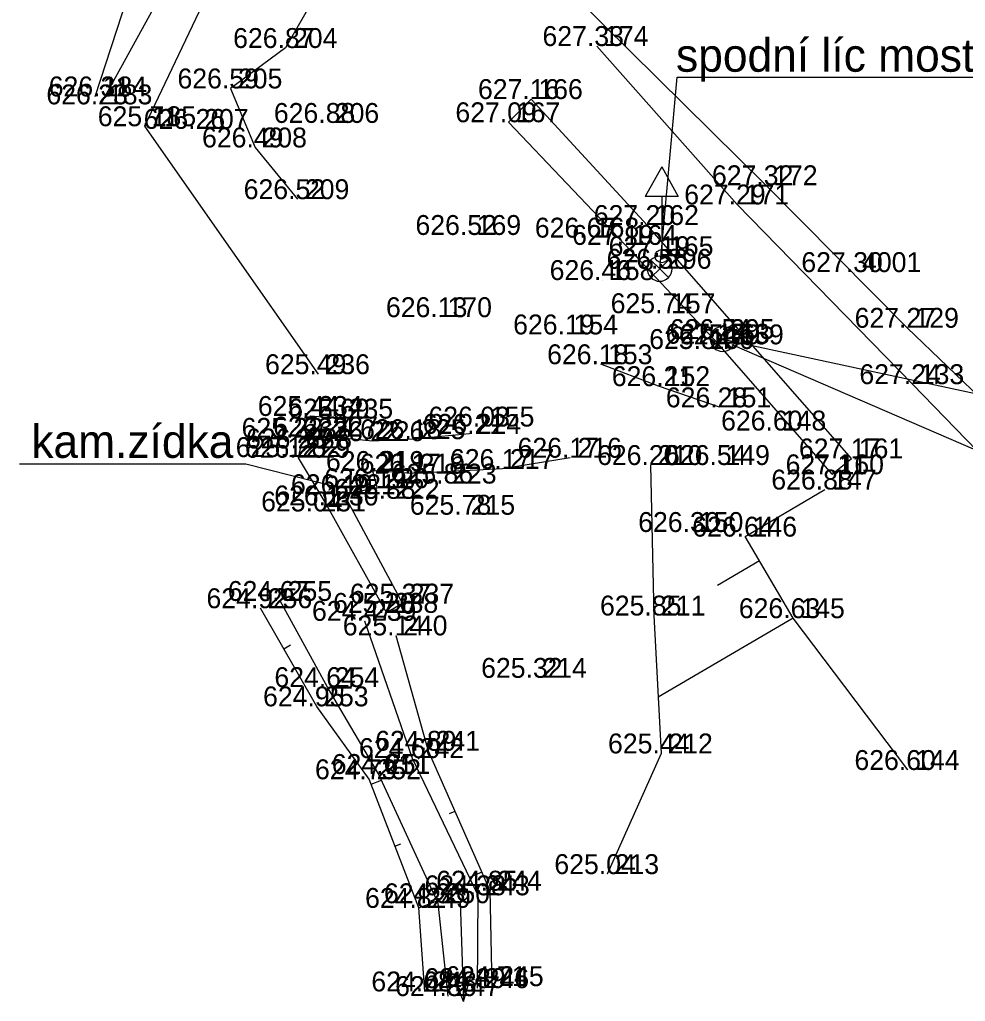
# Model space of a CAD drawing. Extents: x -632073 to -631949, y -1099530 to -1099406.
# Drawn here: x -632009.68 to -631995.42, y -1099504.03 to -1099489.22 of the extents above; entities that cross this region are included whole.
import ezdxf

# ---------------------------------------------------------------- set-up
doc = ezdxf.new("R2010")
doc.units = 0
for name, color, linetype in [('Vrstva 1', 7, 'Continuous'), ('Vrstva 13', 7, 'Continuous'), ('Vrstva 14', 7, 'Continuous'), ('Vrstva 15', 7, 'Continuous'), ('Vrstva 19', 7, 'Continuous'), ('Vrstva 20', 7, 'Continuous'), ('Vrstva 22', 7, 'Continuous'), ('Vrstva 23', 7, 'Continuous'), ('Vrstva 26', 7, 'Continuous'), ('Vrstva 27', 7, 'Continuous'), ('Vrstva 5', 7, 'Continuous'), ('Vrstva 6', 7, 'Continuous'), ('Vrstva 7', 7, 'Continuous'), ('Vrstva 8', 7, 'Continuous'), ('Vrstva 9', 7, 'Continuous')]:
    doc.layers.add(name, color=color, linetype=linetype)

msp = doc.modelspace()

# ---------------------------------------------------------------- linework, layer by layer
at = {"layer": 'Vrstva 1'}
for p, q in [((-631998.86, -1099492.01), (-632000.98, -1099489.62)), ((-631996.22, -1099494.72), (-631998.86, -1099492.01)), ((-631993.26, -1099497.78), (-631996.22, -1099494.72))]:
    msp.add_line(p, q, dxfattribs=at)
at = {"layer": 'Vrstva 13'}
for p, q in [((-632000.98, -1099489.62), (-632000.98, -1099489.62)), ((-632005.67, -1099489.65), (-632005.67, -1099489.65)), ((-632006.5, -1099490.26), (-632006.5, -1099490.26)), ((-632008.54, -1099490.38), (-632008.54, -1099490.38)), ((-632008.46, -1099490.5), (-632008.46, -1099490.5)), ((-632001.97, -1099490.42), (-632001.97, -1099490.42)), ((-632005.04, -1099490.78), (-632005.04, -1099490.78)), ((-632002.31, -1099490.77), (-632002.31, -1099490.77)), ((-632007.8, -1099490.83), (-632007.8, -1099490.83)), ((-632007.01, -1099490.87), (-632007.01, -1099490.87)), ((-632006.13, -1099491.15), (-632006.13, -1099491.15)), ((-631998.43, -1099491.72), (-631998.43, -1099491.72)), ((-632005.49, -1099491.93), (-632005.49, -1099491.93)), ((-631998.86, -1099492.01), (-631998.86, -1099492.01)), ((-632000.22, -1099492.32), (-632000.22, -1099492.32)), ((-632002.9, -1099492.47), (-632002.9, -1099492.47)), ((-632001.12, -1099492.51), (-632001.12, -1099492.51)), ((-632000.55, -1099492.62), (-632000.55, -1099492.62)), ((-632000, -1099492.79), (-632000, -1099492.79)), ((-632000.03, -1099492.98), (-632000.03, -1099492.98)), ((-632000.89, -1099493.15), (-632000.89, -1099493.15)), ((-631997.09, -1099493.03), (-631997.09, -1099493.03)), ((-632003.34, -1099493.71), (-632003.34, -1099493.71)), ((-631999.97, -1099493.65), (-631999.97, -1099493.65)), ((-631996.3, -1099493.87), (-631996.3, -1099493.87)), ((-632001.44, -1099493.97), (-632001.44, -1099493.97)), ((-631999.08, -1099494.04), (-631999.08, -1099494.04)), ((-631999.39, -1099494.19), (-631999.39, -1099494.19)), ((-631999.15, -1099494.11), (-631999.15, -1099494.11)), ((-631998.94, -1099494.12), (-631998.94, -1099494.12)), ((-632000.92, -1099494.42), (-632000.92, -1099494.42)), ((-632005.18, -1099494.57), (-632005.18, -1099494.57)), ((-632000.05, -1099494.75), (-632000.05, -1099494.75)), ((-631996.22, -1099494.72), (-631996.22, -1099494.72)), ((-631999.13, -1099495.07), (-631999.13, -1099495.07)), ((-632005.29, -1099495.2), (-632005.29, -1099495.2)), ((-632004.83, -1099495.24), (-632004.83, -1099495.24)), ((-632002.7, -1099495.36), (-632002.7, -1099495.36)), ((-632005.52, -1099495.53), (-632005.52, -1099495.53)), ((-632005.06, -1099495.51), (-632005.06, -1099495.51)), ((-632002.9, -1099495.47), (-632002.9, -1099495.47)), ((-631998.3, -1099495.42), (-631998.3, -1099495.42)), ((-632005.45, -1099495.69), (-632005.45, -1099495.69)), ((-632004.36, -1099495.58), (-632004.36, -1099495.58)), ((-632003.74, -1099495.55), (-632003.74, -1099495.55)), ((-632005.61, -1099495.82), (-632005.61, -1099495.82)), ((-632005.48, -1099495.83), (-632005.48, -1099495.83)), ((-632001.38, -1099495.83), (-632001.38, -1099495.83)), ((-631997.14, -1099495.84), (-631997.14, -1099495.84)), ((-632000.17, -1099495.94), (-632000.17, -1099495.94)), ((-631999.15, -1099495.94), (-631999.15, -1099495.94)), ((-632004.36, -1099496.03), (-632004.36, -1099496.03)), ((-632003.76, -1099496.07), (-632003.76, -1099496.07)), ((-632002.4, -1099496), (-632002.4, -1099496)), ((-631997.43, -1099496.08), (-631997.43, -1099496.08)), ((-632003.27, -1099496.22), (-632003.27, -1099496.22)), ((-632004.79, -1099496.38), (-632004.79, -1099496.38)), ((-632004.29, -1099496.29), (-632004.29, -1099496.29)), ((-631997.54, -1099496.31), (-631997.54, -1099496.31)), ((-632005.05, -1099496.55), (-632005.05, -1099496.55)), ((-632004.13, -1099496.45), (-632004.13, -1099496.45)), ((-632005.24, -1099496.64), (-632005.24, -1099496.64)), ((-632002.99, -1099496.69), (-632002.99, -1099496.69)), ((-631999.55, -1099496.95), (-631999.55, -1099496.95)), ((-631998.74, -1099497.02), (-631998.74, -1099497.02)), ((-632005.75, -1099497.99), (-632005.75, -1099497.99)), ((-632003.91, -1099498.03), (-632003.91, -1099498.03)), ((-632006.05, -1099498.1), (-632006.05, -1099498.1)), ((-632004.15, -1099498.17), (-632004.15, -1099498.17)), ((-632000.12, -1099498.21), (-632000.12, -1099498.21)), ((-632004.48, -1099498.29), (-632004.48, -1099498.29)), ((-631998.02, -1099498.25), (-631998.02, -1099498.25)), ((-632004.01, -1099498.51), (-632004.01, -1099498.51)), ((-632001.91, -1099499.15), (-632001.91, -1099499.15)), ((-632005.04, -1099499.29), (-632005.04, -1099499.29)), ((-632005.2, -1099499.58), (-632005.2, -1099499.58)), ((-632003.52, -1099500.25), (-632003.52, -1099500.25)), ((-632003.76, -1099500.36), (-632003.76, -1099500.36)), ((-632000.01, -1099500.29), (-632000.01, -1099500.29)), ((-631996.29, -1099500.54), (-631996.29, -1099500.54)), ((-632004.41, -1099500.68), (-632004.41, -1099500.68)), ((-632004.27, -1099500.6), (-632004.27, -1099500.6)), ((-632000.82, -1099502.11), (-632000.82, -1099502.11)), ((-632002.77, -1099502.43), (-632002.77, -1099502.43)), ((-632002.59, -1099502.36), (-632002.59, -1099502.36)), ((-632003.66, -1099502.62), (-632003.66, -1099502.62)), ((-632003.37, -1099502.55), (-632003.37, -1099502.55)), ((-632002.78, -1099503.83), (-632002.78, -1099503.83)), ((-632002.56, -1099503.8), (-632002.56, -1099503.8)), ((-632003.57, -1099503.88), (-632003.57, -1099503.88)), ((-632003.22, -1099503.95), (-632003.22, -1099503.95))]:
    msp.add_line(p, q, dxfattribs=at)
at = {"layer": 'Vrstva 19'}
for p, q in [((-632000, -1099491.44), (-632000.25, -1099491.89)), ((-632000, -1099491.44), (-631999.75, -1099491.89)), ((-631999.75, -1099491.89), (-632000.25, -1099491.89)), ((-632000, -1099491.89), (-632000, -1099492.69))]:
    msp.add_line(p, q, dxfattribs=at)
msp.add_circle((-632000, -1099492.79), 0.1, dxfattribs=at)
at = {"layer": 'Vrstva 20'}
for points in [[(-632003.04, -1099502.531), (-632002.99, -1099504.03), (-632002.878, -1099503.651)], [(-632002.99, -1099504.03), (-632003.127, -1099503.66)]]:
    msp.add_lwpolyline(points, dxfattribs=at)
at = {"layer": 'Vrstva 22'}
for p, q in [((-632009.68, -1099495.92), (-632006.271, -1099495.92)), ((-632006.271, -1099495.92), (-632004.905, -1099496.271))]:
    msp.add_line(p, q, dxfattribs=at)
at = {"layer": 'Vrstva 23'}
for p, q in [((-632000.03, -1099492.98), (-631999.767, -1099490.089)), ((-631999.767, -1099490.089), (-631991.333, -1099490.089)), ((-631999.08, -1099494.04), (-631994.697, -1099494.984)), ((-631998.94, -1099494.12), (-631992.258, -1099497.016))]:
    msp.add_line(p, q, dxfattribs=at)
at = {"layer": 'Vrstva 26'}
for p, q in [((-631998.525, -1099497.387), (-631999.161, -1099497.759)), ((-631998.02, -1099498.25), (-632000.055, -1099499.441)), ((-632005.698, -1099498.713), (-632005.594, -1099498.653)), ((-632004.381, -1099500.755), (-632004.226, -1099500.695)), ((-632003.117, -1099501.165), (-632003.202, -1099501.203)), ((-632004.021, -1099501.687), (-632003.935, -1099501.654)), ((-632002.713, -1099502.08), (-632002.898, -1099502.162)), ((-632003.66, -1099502.62), (-632003.386, -1099502.514))]:
    msp.add_line(p, q, dxfattribs=at)
at = {"layer": 'Vrstva 27'}
for p, q in [((-632005.84, -1099486.73), (-632007.8, -1099490.83)), ((-632004.88, -1099488.26), (-632005.67, -1099489.65)), ((-632007.61, -1099488.96), (-632008.46, -1099490.5)), ((-632005.67, -1099489.65), (-632006.5, -1099490.26)), ((-632006.5, -1099490.26), (-632006.13, -1099491.15)), ((-632007.8, -1099490.83), (-632005.18, -1099494.57)), ((-632006.13, -1099491.15), (-632005.49, -1099491.93)), ((-632000.05, -1099494.75), (-632000.92, -1099494.42)), ((-631999.13, -1099495.07), (-632000.05, -1099494.75)), ((-632000.17, -1099495.94), (-632000.12, -1099498.21)), ((-631998.74, -1099497.02), (-631997.54, -1099496.31)), ((-631998.02, -1099498.25), (-631998.74, -1099497.02)), ((-632005.04, -1099499.29), (-632005.75, -1099497.99)), ((-632005.2, -1099499.58), (-632006.05, -1099498.1)), ((-632000.12, -1099498.21), (-632000.01, -1099500.29)), ((-632004.48, -1099498.29), (-632003.76, -1099500.36)), ((-631996.29, -1099500.54), (-631998.02, -1099498.25)), ((-632004.01, -1099498.51), (-632003.52, -1099500.25)), ((-632004.27, -1099500.6), (-632005.04, -1099499.29)), ((-632004.41, -1099500.68), (-632005.2, -1099499.58)), ((-632003.52, -1099500.25), (-632002.59, -1099502.36)), ((-632003.76, -1099500.36), (-632002.77, -1099502.43)), ((-632000.01, -1099500.29), (-632000.82, -1099502.11)), ((-632003.66, -1099502.62), (-632004.41, -1099500.68)), ((-632003.37, -1099502.55), (-632004.27, -1099500.6)), ((-632002.77, -1099502.43), (-632002.78, -1099503.83)), ((-632003.57, -1099503.88), (-632003.66, -1099502.62)), ((-632003.22, -1099503.95), (-632003.37, -1099502.55))]:
    msp.add_line(p, q, dxfattribs=at)
at = {"layer": 'Vrstva 5'}
msp.add_line((-632008.54, -1099490.38), (-632007.36, -1099486.75), dxfattribs=at)
at = {"layer": 'Vrstva 6'}
for p, q in [((-632000.162, -1099492.848), (-632000.03, -1099492.98)), ((-631999.898, -1099492.848), (-632000.03, -1099492.98)), ((-631999.898, -1099492.848), (-631999.898, -1099492.848)), ((-632000.03, -1099492.98), (-632000.162, -1099493.112)), ((-632000.03, -1099492.98), (-631999.898, -1099493.112)), ((-631999.212, -1099493.908), (-631999.08, -1099494.04)), ((-631998.948, -1099493.908), (-631999.08, -1099494.04)), ((-631998.948, -1099493.908), (-631998.948, -1099493.908)), ((-631999.08, -1099494.04), (-631999.212, -1099494.172)), ((-631999.08, -1099494.04), (-631998.948, -1099494.172))]:
    msp.add_line(p, q, dxfattribs=at)
for centre, start, end in [((-632000.03, -1099492.98), 135, 224.9643), ((-632000.03, -1099492.98), 45, 134.9643), ((-632000.03, -1099492.98), 315, 44.9643), ((-632000.03, -1099492.98), 225, 314.9643), ((-631999.08, -1099494.04), 135, 224.9643), ((-631999.08, -1099494.04), 45, 134.9643), ((-631999.08, -1099494.04), 315, 44.9643), ((-631999.08, -1099494.04), 225, 314.9643)]:
    msp.add_arc(centre, 0.188, start, end, dxfattribs=at)
at = {"layer": 'Vrstva 7'}
for p, q in [((-632001.97, -1099490.42), (-632002.31, -1099490.77)), ((-632000.22, -1099492.32), (-632001.97, -1099490.42)), ((-632000.55, -1099492.62), (-632002.31, -1099490.77)), ((-631997.14, -1099495.84), (-632000.22, -1099492.32)), ((-631999.15, -1099494.11), (-632000.55, -1099492.62)), ((-631997.43, -1099496.08), (-631999.15, -1099494.11)), ((-631997.43, -1099496.08), (-631997.14, -1099495.84))]:
    msp.add_line(p, q, dxfattribs=at)
at = {"layer": 'Vrstva 8'}
for p, q in [((-631998.43, -1099491.72), (-632001.49, -1099488.69)), ((-631996.3, -1099493.87), (-631998.43, -1099491.72)), ((-631993.85, -1099496.22), (-631996.3, -1099493.87))]:
    msp.add_line(p, q, dxfattribs=at)
at = {"layer": 'Vrstva 9'}
for p, q in [((-632005.52, -1099495.53), (-632005.29, -1099495.2)), ((-632005.29, -1099495.2), (-632004.83, -1099495.24)), ((-632005.06, -1099495.51), (-632005.45, -1099495.69)), ((-632004.36, -1099495.58), (-632005.06, -1099495.51)), ((-632002.9, -1099495.47), (-632003.74, -1099495.55)), ((-632005.45, -1099495.69), (-632005.48, -1099495.83)), ((-632003.74, -1099495.55), (-632004.36, -1099495.58)), ((-632005.48, -1099495.83), (-632005.05, -1099496.55)), ((-632001.38, -1099495.83), (-632002.4, -1099496)), ((-632003.76, -1099496.07), (-632004.36, -1099496.03)), ((-632004.36, -1099496.03), (-632004.29, -1099496.29)), ((-632002.4, -1099496), (-632003.76, -1099496.07)), ((-632004.29, -1099496.29), (-632004.79, -1099496.38)), ((-632004.79, -1099496.38), (-632003.91, -1099498.03)), ((-632005.05, -1099496.55), (-632004.15, -1099498.17)), ((-632003.91, -1099498.03), (-632004.15, -1099498.17)), ((-632002.59, -1099502.36), (-632002.56, -1099503.8))]:
    msp.add_line(p, q, dxfattribs=at)

# ---------------------------------------------------------------- texts
at = {"layer": 'Vrstva 14'}
for s, p in [(' 174', (-632000.98, -1099489.62)), (' 204', (-632005.67, -1099489.65)), (' 205', (-632006.5, -1099490.26)), (' 184', (-632008.54, -1099490.38)), (' 183', (-632008.46, -1099490.5)), (' 166', (-632001.97, -1099490.42)), (' 206', (-632005.04, -1099490.78)), (' 167', (-632002.31, -1099490.77)), (' 185', (-632007.8, -1099490.83)), (' 207', (-632007.01, -1099490.87)), (' 208', (-632006.13, -1099491.15)), (' 172', (-631998.43, -1099491.72)), (' 209', (-632005.49, -1099491.93)), (' 171', (-631998.86, -1099492.01)), (' 162', (-632000.22, -1099492.32)), (' 169', (-632002.9, -1099492.47)), (' 168', (-632001.12, -1099492.51)), (' 164', (-632000.55, -1099492.62)), (' 165', (-632000, -1099492.79)), (' 296', (-632000.03, -1099492.98)), (' 4001', (-631997.09, -1099493.03)), (' 158', (-632000.89, -1099493.15)), (' 170', (-632003.34, -1099493.71)), (' 157', (-631999.97, -1099493.65)), (' 129', (-631996.3, -1099493.87)), (' 154', (-632001.44, -1099493.97)), (' 295', (-631999.08, -1099494.04)), (' 156', (-631999.39, -1099494.19)), (' 163', (-631999.15, -1099494.11)), (' 159', (-631998.94, -1099494.12)), (' 153', (-632000.92, -1099494.42)), (' 236', (-632005.18, -1099494.57)), (' 152', (-632000.05, -1099494.75)), (' 133', (-631996.22, -1099494.72)), (' 151', (-631999.13, -1099495.07)), (' 234', (-632005.29, -1099495.2)), (' 235', (-632004.83, -1099495.24)), (' 155', (-632002.7, -1099495.36)), (' 233', (-632005.52, -1099495.53)), (' 227', (-632005.06, -1099495.51)), (' 225', (-632003.74, -1099495.55)), (' 224', (-632002.9, -1099495.47)), (' 148', (-631998.3, -1099495.42)), (' 228', (-632005.45, -1099495.69)), (' 226', (-632004.36, -1099495.58)), (' 232', (-632005.61, -1099495.82)), (' 229', (-632005.48, -1099495.83)), (' 216', (-632001.38, -1099495.83)), (' 161', (-631997.14, -1099495.84)), (' 210', (-632000.17, -1099495.94)), (' 149', (-631999.15, -1099495.94)), (' 219', (-632004.36, -1099496.03)), (' 218', (-632003.76, -1099496.07)), (' 217', (-632002.4, -1099496)), (' 160', (-631997.43, -1099496.08)), (' 220', (-632004.29, -1099496.29)), (' 223', (-632003.27, -1099496.22)), (' 221', (-632004.79, -1099496.38)), (' 147', (-631997.54, -1099496.31)), (' 230', (-632005.05, -1099496.55)), (' 222', (-632004.13, -1099496.45)), (' 231', (-632005.24, -1099496.64)), (' 215', (-632002.99, -1099496.69)), (' 150', (-631999.55, -1099496.95)), (' 146', (-631998.74, -1099497.02)), (' 255', (-632005.75, -1099497.99)), (' 237', (-632003.91, -1099498.03)), (' 256', (-632006.05, -1099498.1)), (' 238', (-632004.15, -1099498.17)), (' 211', (-632000.12, -1099498.21)), (' 239', (-632004.48, -1099498.29)), (' 145', (-631998.02, -1099498.25)), (' 240', (-632004.01, -1099498.51)), (' 214', (-632001.91, -1099499.15)), (' 254', (-632005.04, -1099499.29)), (' 253', (-632005.2, -1099499.58)), (' 241', (-632003.52, -1099500.25)), (' 212', (-632000.01, -1099500.29)), (' 242', (-632003.76, -1099500.36)), (' 144', (-631996.29, -1099500.54)), (' 252', (-632004.41, -1099500.68)), (' 251', (-632004.27, -1099500.6)), (' 213', (-632000.82, -1099502.11)), (' 244', (-632002.59, -1099502.36)), (' 243', (-632002.77, -1099502.43)), (' 249', (-632003.66, -1099502.62)), (' 250', (-632003.37, -1099502.55)), (' 246', (-632002.78, -1099503.83)), (' 245', (-632002.56, -1099503.8)), (' 248', (-632003.57, -1099503.88)), (' 247', (-632003.22, -1099503.95))]:
    msp.add_text(s, height=0.3, dxfattribs=at).set_placement(p)
at = {"layer": 'Vrstva 15'}
for s, p in [('627.33 ', (-632001.797, -1099489.62)), ('626.87 ', (-632006.461, -1099489.65)), ('626.59 ', (-632007.3, -1099490.26)), ('626.23 ', (-632009.277, -1099490.5)), ('626.31 ', (-632009.242, -1099490.38)), ('627.16 ', (-632002.77, -1099490.42)), ('626.88 ', (-632005.847, -1099490.78)), ('627.09 ', (-632003.11, -1099490.77)), ('625.71 ', (-632008.502, -1099490.83)), ('626.26 ', (-632007.809, -1099490.87)), ('626.49 ', (-632006.93, -1099491.15)), ('627.32 ', (-631999.242, -1099491.72)), ('626.52 ', (-632006.302, -1099491.93)), ('627.29 ', (-631999.66, -1099492.01)), ('627.20 ', (-632001.024, -1099492.32)), ('626.52 ', (-632003.712, -1099492.47)), ('626.67 ', (-632001.912, -1099492.51)), ('627.19 ', (-632001.35, -1099492.62)), ('627.19 ', (-632000.8, -1099492.79)), ('626.56 ', (-632000.83, -1099492.98)), ('627.30 ', (-631997.894, -1099493.03)), ('626.46 ', (-632001.689, -1099493.15)), ('626.13 ', (-632004.157, -1099493.71)), ('625.74 ', (-632000.769, -1099493.65)), ('627.27 ', (-631997.091, -1099493.87)), ('626.19 ', (-632002.239, -1099493.97)), ('626.54 ', (-631999.879, -1099494.04)), ('625.84 ', (-632000.188, -1099494.19)), ('627.17 ', (-631999.941, -1099494.11)), ('625.89 ', (-631999.739, -1099494.12)), ('626.18 ', (-632001.727, -1099494.42)), ('625.49 ', (-632005.98, -1099494.57)), ('626.21 ', (-632000.752, -1099494.75)), ('627.24 ', (-631997.019, -1099494.72)), ('626.28 ', (-631999.937, -1099495.07)), ('625.44 ', (-632006.089, -1099495.2)), ('625.69 ', (-632005.63, -1099495.24)), ('626.03 ', (-632003.517, -1099495.36)), ('625.22 ', (-632006.333, -1099495.53)), ('626.24 ', (-632005.858, -1099495.51)), ('626.18 ', (-632004.547, -1099495.55)), ('626.21 ', (-632003.602, -1099495.47)), ('626.60 ', (-631999.104, -1099495.42)), ('626.23 ', (-632006.267, -1099495.69)), ('626.22 ', (-632005.173, -1099495.58)), ('625.12 ', (-632006.422, -1099495.82)), ('626.20 ', (-632006.284, -1099495.83)), ('626.17 ', (-632002.172, -1099495.83)), ('627.17 ', (-631997.931, -1099495.84)), ('626.20 ', (-632000.974, -1099495.94)), ('626.54 ', (-631999.949, -1099495.94)), ('626.21 ', (-632005.062, -1099496.03)), ('626.17 ', (-632004.552, -1099496.07)), ('626.17 ', (-632003.192, -1099496)), ('627.11 ', (-631998.132, -1099496.08)), ('626.19 ', (-632005.089, -1099496.29)), ('625.86 ', (-632004.069, -1099496.22)), ('626.19 ', (-632005.589, -1099496.38)), ('626.88 ', (-631998.347, -1099496.31)), ('626.17 ', (-632005.842, -1099496.55)), ('625.88 ', (-632004.937, -1099496.45)), ('625.04 ', (-632006.038, -1099496.64)), ('625.78 ', (-632003.797, -1099496.69)), ('626.30 ', (-632000.354, -1099496.95)), ('626.64 ', (-631999.539, -1099497.02)), ('624.67 ', (-632006.542, -1099497.99)), ('625.37 ', (-632004.701, -1099498.03)), ('624.92 ', (-632006.863, -1099498.1)), ('625.20 ', (-632004.955, -1099498.17)), ('625.85 ', (-632000.93, -1099498.21)), ('624.47 ', (-632005.272, -1099498.29)), ('626.63 ', (-631998.837, -1099498.25)), ('625.14 ', (-632004.808, -1099498.51)), ('625.32 ', (-632002.722, -1099499.15)), ('624.64 ', (-632005.839, -1099499.29)), ('624.95 ', (-632006.01, -1099499.58)), ('624.89 ', (-632004.32, -1099500.25)), ('625.44 ', (-632000.809, -1099500.29)), ('624.60 ', (-632004.564, -1099500.36)), ('626.60 ', (-631997.094, -1099500.54)), ('624.73 ', (-632005.227, -1099500.68)), ('624.61 ', (-632004.974, -1099500.6)), ('625.04 ', (-632001.618, -1099502.11)), ('624.85 ', (-632003.4, -1099502.36)), ('624.38 ', (-632003.577, -1099502.43)), ('624.82 ', (-632004.472, -1099502.62)), ('624.33 ', (-632004.187, -1099502.55)), ('624.39 ', (-632003.579, -1099503.83)), ('624.71 ', (-632003.263, -1099503.8)), ('624.68 ', (-632004.377, -1099503.88)), ('624.36 ', (-632004.019, -1099503.95))]:
    msp.add_text(s, height=0.3, dxfattribs=at).set_placement(p)
at = {"layer": 'Vrstva 22'}
msp.add_text('kam.zídka', height=0.5, dxfattribs=at).set_placement((-632009.504, -1099495.832))
at = {"layer": 'Vrstva 23'}
msp.add_text('spodní líc mostovky:626,56', height=0.5, dxfattribs=at).set_placement((-631999.784, -1099490.008))

doc.saveas('drawing.dxf')
